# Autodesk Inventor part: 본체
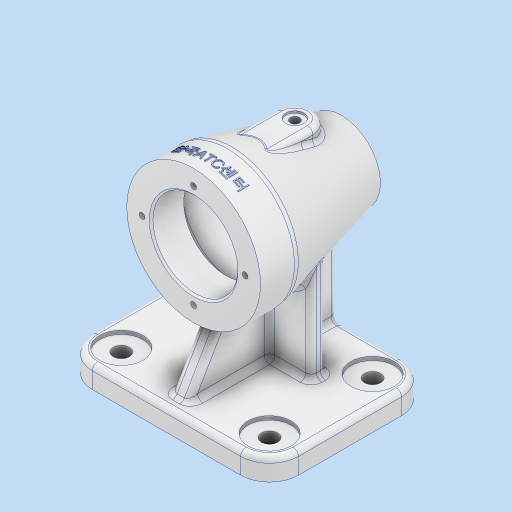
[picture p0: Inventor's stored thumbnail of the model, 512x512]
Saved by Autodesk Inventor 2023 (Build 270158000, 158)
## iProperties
Created: 2024-12
Part Number: 본체
Material: 알루미늄 6061
Document SubType Name: Modeling
Designer: asung
Density: 2.7 g/cm^3
Appearance: 알루미늄 - 평지
Mass: 739.309 g
Surface Area: 673.847 cm^2
Volume: 273.818 cm^3
Author: asung
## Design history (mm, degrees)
sketch "스케치1"
  geometry: L1 (41, -44.5)-(-41, -44.5); L2 (-57, -28.5)-(-57, 28.5); L3 (-41, 44.5)-(41, 44.5); L4 (57, 28.5)-(57, -28.5); L5 (57, -44.5)-(-57, 44.5); L6 (-57, -44.5)-(57, 44.5); A1 r 16 centre (41, 28.5) between (57, 28.5) and (41, 44.5); A2 r 16 centre (-41, 28.5) between (-41, 44.5) and (-57, 28.5); A3 r 16 centre (-41, -28.5) between (-57, -28.5) and (-41, -44.5); A4 r 16 centre (41, -28.5) between (41, -44.5) and (57, -28.5); 1 further point
  constraints: 12 end point, 8 point on circle, 8 point on line, 8 tangent, 4 centre point, 3 equal radius, 2 midpoint, 2 parallel, 1 horizontal, 1 perpendicular
  dimensions: "d0" = 114 distance of L5.end L6.end; "d1" = 89 distance of L6.start L5.end; "d2" = 16 radius of A1
extrude "돌출1" new body sketch "스케치1" distance "d3" = 12; taper "d4" = 0 deg
node "작업 평면1"
sketch "스케치2"
  geometry: L1 (-16, 0)-(-16, 12) reference; L2 (-16, 12)-(73, 12) reference; L3 (73, 12)-(73, 0) reference; L4 (73, 0)-(-16, 0) reference; L5 (73, 0)-(73, 82); L6 (83, 82)-(-1, 82); L7 (-1, 82)-(-1, 119); L8 (-1, 119)-(19, 119); L9 (19, 119)-(83, 103); L10 (83, 103)-(83, 82); L11 (83, 0)-(83, 82); 1 further point
  constraints: 14 end point, 2 parallel, 2 perpendicular, 1 horizontal, 1 vertical
  dimensions: "d5" = 82 distance of L5.end L3.end; "d6" = 84 distance of L6.start L6.end; "d7" = 20 distance of L7.end L8.end; "d8" = 74 diameter of L8 L6; "d9" = 42 diameter of L9.end L6; "d81" = 10 distance between parallel lines of L5 L11; "d82" = 10 distance between parallel lines of L3 L10; "d83" = 164 diameter of L4 L6; "d84" = 82 distance from line of L11.end L4; "d85" = 0 distance from line of L11.start L4
revolve "회전1" sketch "스케치2" stored, may be unused: angle "d10" = 90 deg
sketch "스케치3"
  geometry: C1 r 37 at (0, 0) reference; 2 further points
  constraints: 1 coincident
hole "구멍1" sketch "스케치3" at (0, 0) diameter "d11" = 47; stored, may be unused: countersink angle "d15" = 90 deg, drill point angle "d17" = 0 deg; dims "d12" = 6, "d13" = 4, "d14" = 2, "d16" = 18
sketch "스케치4"
  geometry: L1 (83, 103)-(83, 61) reference; L2 (83, 61)-(19, 45) reference; L3 (19, 45)-(-1, 45) reference; L4 (-1, 45)-(-1, 58.5) reference; L5 (-1, 58.5)-(17, 58.5) reference; L6 (17, 58.5)-(17, 105.5) reference; L7 (17, 105.5)-(-1, 105.5) reference; L8 (-1, 105.5)-(-1, 119) reference; L9 (-1, 119)-(19, 119) reference; L10 (19, 119)-(83, 103) reference; L11 (-16, 0)-(-16, 12) reference; L12 (-16, 12)-(73, 12) reference; L13 (73, 12)-(73, 0) reference; L14 (73, 0)-(-16, 0) reference; L15 (-1, 58.5)-(-1, 105.5) reference; L16 (83, 103)-(83, 61) reference; L17 (83, 82)-(-1, 82); L18 (105.569, 111)-(97.569, 111); L19 (75, 82)-(75, 97.5); L20 (75, 97.5)-(72, 97.5); L21 (72, 97.5)-(72, 99.5); L22 (72, 99.5)-(62, 99.5); L23 (62, 99.5)-(62, 103.096); L24 (17, 105.5)-(17, 58.5) reference; L25 (62, 103.096)-(17, 114.346); L26 (17, 105.5)-(17, 114.346); 5 further points
  constraints: 18 end point, 4 perpendicular, 3 midpoint, 2 vertical, 1 horizontal, 1 point on line
  dimensions: "d20" = 8 distance of L18.start L18.end; "d21" = 8 distance between parallel lines of L1 L19; "d22" = 31 diameter of L19.end L17; "d23" = 35 diameter of L22 L17; "d24" = 3 distance of L19.end L20.end; "d25" = 10 distance of L21.end L22.end; "d30" = 111 distance between parallel lines of L14 L18; "d31" = 22.5688 distance from line of L18.start L16; "d118" = 5 distance between parallel lines of L10 L25
revolve "회전2" sketch "스케치4" stored, may be unused: angle "d32" = 90 deg
fillet "모깎기1" dims "d33" = 3
fillet "모깎기2" dims "d34" = 0.3
fillet "모깎기4" dims "d36" = 3
chamfer "모따기1" distance "d38" = 1; stored, may be unused: second distance "d39" = 2, angle "d40" = 45 deg
node "작업 평면2"
sketch "스케치5" dims "d42" = 20
  geometry: L1 (16.733, 29.5)-(16.733, 9.5) reference; L2 (-16.733, 9.5)-(-16.733, 29.5) reference; L3 (-16.733, 29.5)-(16.733, 29.5) reference; L4 (-10, -26.5)-(-10, -0.572); L5 (10, -26.5)-(10, -0.572); 4 further points
  constraints: 4 end point, 2 vertical, 1 midpoint, 1 parallel, 1 vertical alignment, 6 other
  dimensions: "d43" = 56 distance from line of L3 point (0, -26.5); "d44" = 20 distance between parallel lines of L4 L5; "d45" = 56 distance from line of L5.start L3
extrude "돌출2" join sketch "스케치5" stored distance "d46" = 10; taper "d47" = 0 deg
fillet "모깎기6" dims "d48" = 3
fillet "모깎기7" dims "d49" = 3
sketch "스케치6"
  geometry: A1 r 7 centre (0, 26.5) between (7, 26.5) and (-7, 26.5) reference; 2 further points
  constraints: 1 coincident
hole "구멍2" sketch "스케치6" at (0, 26.5) diameter "d50" = 10; stored, may be unused: countersink angle "d54" = 90 deg, drill point angle "d56" = 0 deg; dims "d51" = 6, "d52" = 4, "d53" = 2, "d55" = 1
sketch "스케치7"
  geometry: C1 r 5 at (0, 0) reference; 2 further points
  constraints: 1 coincident
hole "구멍3" sketch "스케치7" at (0, 0) diameter "d57" = 5.1881; stored, may be unused: countersink angle "d61" = 90 deg, drill point angle "d63" = 118 deg; dims "d58" = 12, "d59" = 4, "d60" = 2, "d62" = 16
sketch "스케치8" dims "d64" = 57
  geometry: C1 r 23.5 at (0, 0) reference; C2 r 37 at (0, 0) reference; 3 further points
  constraints: 2 vertical alignment, 1 coincident, 2 other
hole "구멍4" sketch "스케치8" at (0, 28.5) diameter "d65" = 3.242; stored, may be unused: countersink angle "d69" = 90 deg, drill point angle "d71" = 118 deg; dims "d66" = 8, "d67" = 4, "d68" = 2, "d70" = 10
sketch "스케치9"
  geometry: L1 (41, 44.5)-(-41, 44.5) reference; L2 (-28, 15.5)-(28, 15.5); L3 (28, 15.5)-(28, 7.5); L4 (28, 7.5)-(-28, 7.5); L5 (-28, 7.5)-(-28, 15.5); L6 (-28, 15.5)-(28, 7.5); L7 (28, 15.5)-(-28, 7.5); 2 further points
  constraints: 12 end point, 2 midpoint, 2 parallel, 1 horizontal, 1 perpendicular, 1 vertical alignment
  dimensions: "d75" = 29 distance from line of L2.start L1; "d76" = 8 distance of L4.end L2.start; "d77" = 56 distance between parallel lines of L3 L5
extrude "돌출3" join sketch "스케치9" stored distance "d78" = 10; taper "d79" = 0 deg
fillet "모깎기9" dims "d87" = 3
fillet "모깎기10" dims "d88" = 10
sketch "스케치10"
  geometry: L1 (9.974, 110.5)-(9, 112.121) reference; L2 (9, 112.121)-(-1, 112.121) reference; L3 (-1, 112.121)-(-1, 119) reference; L4 (-1, 119)-(17.769, 119) reference; L5 (20.194, 118.701)-(34.642, 115.09) reference; L6 (35.369, 115)-(50, 115) reference; L7 (50, 115)-(50, 114) reference; L8 (50, 114)-(52.406, 114) reference; L9 (52.406, 114)-(52.406, 105.495) reference; L10 (17, 105.5)-(-1, 105.5) reference; L11 (-1, 105.5)-(-1, 108.879) reference; L12 (-1, 108.879)-(9, 108.879) reference; L13 (9, 108.879)-(9.974, 110.5) reference; L14 (63, 64.5)-(71.7, 64.5) reference; L15 (72, 64.8)-(72, 66.5) reference; L16 (75, 69.5)-(75, 94.5) reference; L17 (72, 97.5)-(72, 99.2) reference; L18 (71.7, 99.5)-(63, 99.5) reference; L19 (63, 99.5)-(62, 100.5) reference; L20 (62, 100.5)-(62, 100.754) reference; L21 (57.594, 104.198)-(57.594, 114) reference; L22 (57.594, 114)-(60, 114) reference; L23 (60, 114)-(60, 115) reference; L24 (60, 115)-(62, 115) reference; L25 (65, 112)-(65, 109.842) reference; L26 (67.272, 106.932)-(80.728, 103.568) reference; L27 (83, 100.658)-(83, 63.342) reference; L28 (80.728, 60.432)-(44, 51.25) reference; L29 (44, 51.25)-(44, 12) reference; L30 (44, 12)-(73, 12) reference; L31 (73, 12)-(73, 0) reference; L32 (73, 0)-(-16, 0) reference; L33 (-16, 0)-(-16, 12) reference; L34 (-16, 12)-(36, 12) reference; L35 (36, 12)-(36, 49.25) reference; L36 (36, 49.25)-(20.194, 45.299) reference; L37 (17.769, 45)-(-1, 45) reference; L38 (-1, 45)-(-1, 51.879) reference; L39 (-1, 51.879)-(9, 51.879) reference; L40 (9, 51.879)-(9.974, 53.5) reference; L41 (9.974, 53.5)-(9, 55.121) reference; L42 (9, 55.121)-(-1, 55.121) reference; L43 (-1, 55.121)-(-1, 58.5) reference; L44 (-1, 58.5)-(17, 58.5) reference; L45 (62, 63.246)-(62, 63.5) reference; L46 (62, 63.5)-(63, 64.5) reference; L47 (73, 12)-(73, 58.5); L48 (-9, 12)-(10.053, 45); L49 (52.406, 105.495)-(17, 114.346) reference; L50 (17, 114.346)-(17, 105.5) reference; L51 (59.728, 103.664)-(57.594, 104.198) reference; L52 (17, 58.5)-(17, 49.654) reference; L53 (17, 49.654)-(59.728, 60.336) reference; A1 r 10 centre (17.769, 109) between (20.194, 118.701) and (17.769, 119) reference; A2 r 0.3 centre (71.7, 64.8) between (71.7, 64.5) and (72, 64.8) reference; A3 r 3 centre (72, 69.5) between (72, 66.5) and (75, 69.5) reference; A4 r 3 centre (72, 94.5) between (75, 94.5) and (72, 97.5) reference; A5 r 0.3 centre (71.7, 99.2) between (72, 99.2) and (71.7, 99.5) reference; A6 r 3 centre (59, 100.754) between (62, 100.754) and (59.728, 103.664) reference; A7 r 3 centre (62, 112) between (65, 112) and (62, 115) reference; A8 r 3 centre (80, 100.658) between (83, 100.658) and (80.728, 103.568) reference; A9 r 3 centre (80, 63.342) between (80.728, 60.432) and (83, 63.342) reference; A10 r 10 centre (17.769, 55) between (17.769, 45) and (20.194, 45.299) reference; A11 r 3 centre (59, 63.246) between (59.728, 60.336) and (62, 63.246) reference; 1 further point
  constraints: 4 end point, 3 point on line, 1 vertical, 2 other
  dimensions: "d89" = 7 distance from line of L33 L48.start; "d90" = 60 deg angle of L34 L48
  node "절단 모서리 투영4"
feature "리브1" dims "d91" = 1, "d92" = 10, "d93" = 0, "d94" = 0, "d95" = 1, "d96" = 1
feature "리브2" dims "d97" = 1, "d98" = 10, "d99" = 0, "d100" = 0, "d101" = 1, "d102" = 1
fillet "모깎기11" dims "d103" = 3
fillet "모깎기13" dims "d105" = 3
fillet "모깎기14" dims "d106" = 3
fillet "모깎기15" dims "d107" = 3
sketch "스케치11"
  geometry: A1 r 13 centre (41, -28.5) between (41, -41.5) and (54, -28.5) reference; A2 r 13 centre (-41, -28.5) between (-54, -28.5) and (-41, -41.5) reference; A3 r 13 centre (41, 28.5) between (54, 28.5) and (41, 41.5) reference; A4 r 13 centre (-41, 28.5) between (-41, 41.5) and (-54, 28.5) reference; 5 further points
  constraints: 4 coincident
hole "구멍5" sketch "스케치11" at (41, -28.5), (-41, -28.5), (41, 28.5), (-41, 28.5) diameter "d108" = 9; stored, may be unused: countersink angle "d112" = 90 deg, drill point angle "d114" = 0 deg; dims "d109" = 8, "d110" = 24, "d111" = 2, "d113" = 12
node "작업 평면3"
sketch "스케치12"
  geometry: L1 (0, 8.769)-(0, -10) reference; L2 (-37, -10)-(37, -10) reference; 2 further points
  constraints: 1 vertical alignment, 1 other
  dimensions: "d115" = 9 distance from line of L2 point (0, -1)
feature "엠보싱1" sketch "스케치12" dims "d116" = 0.5, "d117" = 0
fillet "모깎기16" dims "d119" = 5
chamfer "모따기2" distance "d120" = 1; stored, may be unused: second distance "d121" = 2, angle "d122" = 45 deg
feature "Ҏ耀Ґ耀Ғ耀Ҕ耀Җ耀Ҙ耀Қ耀Ҝ耀" dims "d0" = 114, "d1" = 89, "d2" = 16, "d3" = 12, "d4" = 0, "d5" = 82, "d6" = 84, "d7" = 20, "d8" = 74, "d9" = 42, "d10" = 90 deg, "d11" = 47, "d12" = 6, "d13" = 4, "d14" = 2, "d15" = 90 deg, "d16" = 18, "d17" = 0, "d20" = 8, "d21" = 8, "d22" = 31, "d23" = 35, "d24" = 3, "d25" = 10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
node "솔리드1"
pattern_circular "원형 패턴1" dims angle "d73" = 360 deg
node "절단 모서리 투영1"
node "절단 모서리 투영2"
node "절단 모서리 투영3"
node "절단 모서리 투영5"
feature "A9D066F2-1C7D-4E18-AEED-F7BC21143FA4" dims "d11" = 47, "d12" = 6, "d13" = 4, "d14" = 2, "d15" = 90 deg, "d16" = 18, "d17" = 0
